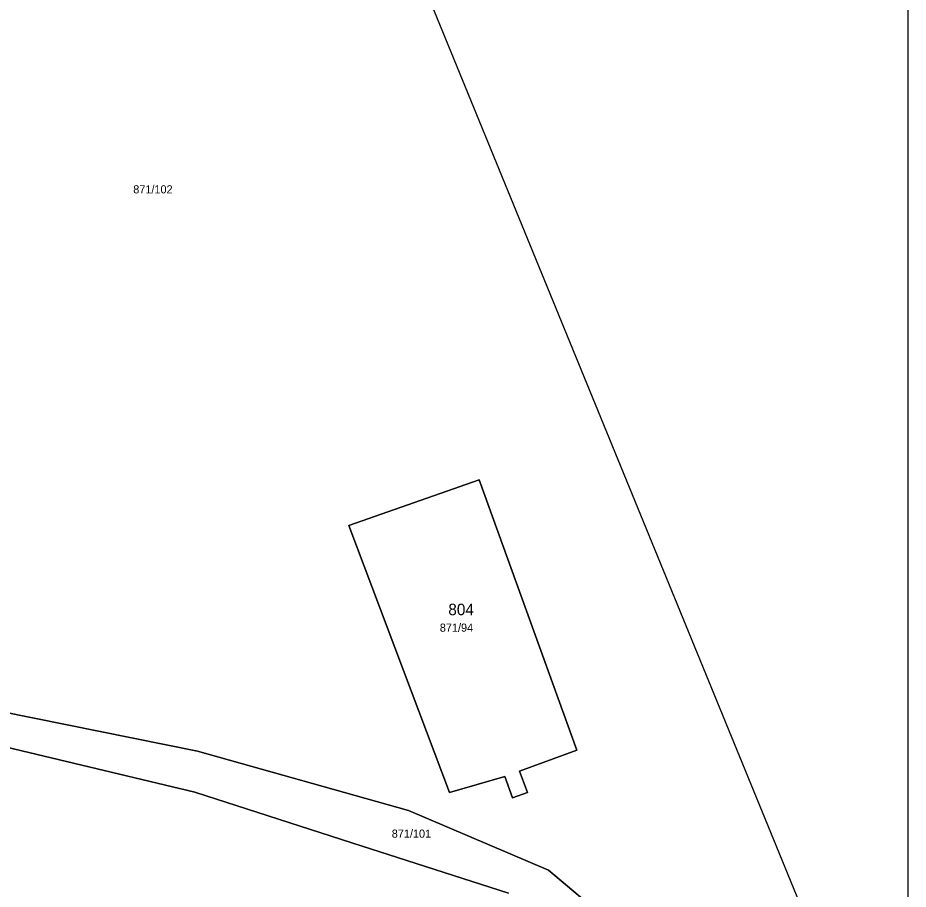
# Model space of a CAD drawing. Extents: x -873642 to -872917, y -1012962 to -1012567.
# Drawn here: x -873009.9 to -872916.9, y -1012787.3 to -1012696.3 of the extents above; entities that cross this region are included whole.
import ezdxf

# ---------------------------------------------------------------- set-up
doc = ezdxf.new("R2010")
doc.units = 0
for name, color, linetype in [('adresni_misto', 7, 'Continuous'), ('cisla_parcelni_kn', 7, 'Continuous'), ('cislo_domovni', 7, 'Continuous'), ('parcely_kn', 7, 'Continuous'), ('stavebni_objekty_bydleni', 7, 'Continuous')]:
    doc.layers.add(name, color=color, linetype=linetype)

msp = doc.modelspace()

# ---------------------------------------------------------------- linework, layer by layer
at = {"layer": 'adresni_misto'}
msp.add_line((-872963.36, -1012759.6), (-872963.36, -1012759.6), dxfattribs=at)
at = {"layer": 'parcely_kn'}
msp.add_line((-872916.927, -1012790.313), (-872916.927, -1012637.66), dxfattribs=at)
msp.add_line((-872916.927, -1012790.313), (-872916.927, -1012637.66), dxfattribs=at)
for points in [[(-873026.14, -1012645.58), (-872990.98, -1012635.74), (-872982.62, -1012656.13), (-872990.41, -1012671.31), (-872972.67, -1012680.42), (-872927.45, -1012790.77)], [(-873026.14, -1012645.58), (-872990.98, -1012635.74), (-872982.62, -1012656.13), (-872990.41, -1012671.31), (-872972.67, -1012680.42), (-872927.45, -1012790.77)], [(-872916.927, -1012637.66), (-872945.94, -1012694.15), (-872972.67, -1012680.42), (-872927.45, -1012790.77), (-872916.927, -1012790.313)], [(-872916.927, -1012637.66), (-872945.94, -1012694.15), (-872972.67, -1012680.42), (-872927.45, -1012790.77), (-872916.927, -1012790.313)], [(-872958.67, -1012787.72), (-872975.04, -1012782.47), (-872991.42, -1012777.17), (-873018.29, -1012770.78), (-873034.35, -1012766.02), (-873054.3, -1012761.9), (-873065.25, -1012758.5), (-873079.89, -1012751.4), (-873100.03, -1012737.92), (-873105.65, -1012736.17), (-873101.03, -1012731.11), (-873099.7, -1012729.49), (-873098.43, -1012730.03), (-873097.94, -1012733.42), (-873081.4, -1012745.11), (-873078.44, -1012747.33), (-873067.46, -1012753.38), (-873059.91, -1012755.24), (-873032.7, -1012762.55), (-873015.14, -1012768.05), (-872991.17, -1012772.9), (-872969.11, -1012779.09), (-872954.48, -1012785.31), (-872943.22, -1012794.81)], [(-872958.67, -1012787.72), (-872975.04, -1012782.47), (-872991.42, -1012777.17), (-873018.29, -1012770.78), (-873034.35, -1012766.02), (-873054.3, -1012761.9), (-873065.25, -1012758.5), (-873079.89, -1012751.4), (-873100.03, -1012737.92), (-873105.65, -1012736.17), (-873101.03, -1012731.11), (-873099.7, -1012729.49), (-873098.43, -1012730.03), (-873097.94, -1012733.42), (-873081.4, -1012745.11), (-873078.44, -1012747.33), (-873067.46, -1012753.38), (-873059.91, -1012755.24), (-873032.7, -1012762.55), (-873015.14, -1012768.05), (-872991.17, -1012772.9), (-872969.11, -1012779.09), (-872954.48, -1012785.31), (-872943.22, -1012794.81)], [(-873185.58, -1012756.25), (-873148.18, -1012749.22), (-873135.01, -1012746.72), (-873122.26, -1012744.11), (-873114.5, -1012741.96), (-873110.07, -1012739.5), (-873105.65, -1012736.17), (-873100.03, -1012737.92), (-873079.89, -1012751.4), (-873065.25, -1012758.5), (-873054.3, -1012761.9), (-873034.35, -1012766.02), (-873018.29, -1012770.78), (-872991.42, -1012777.17), (-872975.04, -1012782.47), (-872958.67, -1012787.72)], [(-873185.58, -1012756.25), (-873148.18, -1012749.22), (-873135.01, -1012746.72), (-873122.26, -1012744.11), (-873114.5, -1012741.96), (-873110.07, -1012739.5), (-873105.65, -1012736.17), (-873100.03, -1012737.92), (-873079.89, -1012751.4), (-873065.25, -1012758.5), (-873054.3, -1012761.9), (-873034.35, -1012766.02), (-873018.29, -1012770.78), (-872991.42, -1012777.17), (-872975.04, -1012782.47), (-872958.67, -1012787.72)], [(-872943.22, -1012794.81), (-872954.48, -1012785.31), (-872969.11, -1012779.09), (-872991.17, -1012772.9), (-873015.14, -1012768.05)], [(-872943.22, -1012794.81), (-872954.48, -1012785.31), (-872969.11, -1012779.09), (-872991.17, -1012772.9), (-873015.14, -1012768.05)]]:
    msp.add_lwpolyline(points, dxfattribs=at)
for points in [[(-872961.74, -1012744.57), (-872951.53, -1012772.79), (-872957.51, -1012774.98), (-872956.69, -1012777.2), (-872958.26, -1012777.75), (-872959.05, -1012775.53), (-872964.82, -1012777.22), (-872975.36, -1012749.35)], [(-872964.82, -1012777.22), (-872959.05, -1012775.53), (-872958.26, -1012777.75), (-872956.69, -1012777.2), (-872957.51, -1012774.98), (-872951.53, -1012772.79), (-872961.74, -1012744.57), (-872975.36, -1012749.35)], [(-872961.74, -1012744.57), (-872951.53, -1012772.79), (-872957.51, -1012774.98), (-872956.69, -1012777.2), (-872958.26, -1012777.75), (-872959.05, -1012775.53), (-872964.82, -1012777.22), (-872975.36, -1012749.35)], [(-872964.82, -1012777.22), (-872959.05, -1012775.53), (-872958.26, -1012777.75), (-872956.69, -1012777.2), (-872957.51, -1012774.98), (-872951.53, -1012772.79), (-872961.74, -1012744.57), (-872975.36, -1012749.35)]]:
    msp.add_lwpolyline(points, close=True, dxfattribs=at)
at = {"layer": 'stavebni_objekty_bydleni'}
msp.add_lwpolyline([(-872961.74, -1012744.57), (-872951.53, -1012772.79), (-872957.51, -1012774.98), (-872956.69, -1012777.2), (-872958.26, -1012777.75), (-872959.05, -1012775.53), (-872964.82, -1012777.22), (-872975.36, -1012749.35)], close=True, dxfattribs=at)

# ---------------------------------------------------------------- texts
at = {"layer": 'cisla_parcelni_kn'}
for s, p in [('871/102', (-872997.865, -1012714.675)), ('871/102', (-872997.865, -1012714.675)), ('871/94', (-872965.846, -1012760.425)), ('871/94', (-872965.846, -1012760.425)), ('871/101', (-872970.865, -1012781.925)), ('871/101', (-872970.865, -1012781.925))]:
    msp.add_text(s, height=0.85, dxfattribs=at).set_placement(p)
at = {"layer": 'cislo_domovni'}
msp.add_text('804', height=1.2, dxfattribs=at).set_placement((-872964.96, -1012758.7))

doc.saveas('drawing.dxf')
